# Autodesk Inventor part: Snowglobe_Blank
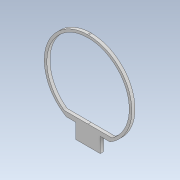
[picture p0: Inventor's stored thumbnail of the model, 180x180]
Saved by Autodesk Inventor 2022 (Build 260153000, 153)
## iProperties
Created: 2021-12
Part Number: Snowglobe_Blank
Material: Generic
Document SubType Name: Modeling
Designer: allis
Density: 1 g/cm^3
Appearance: Default
Author: allis
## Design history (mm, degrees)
sketch "Sketch1"
  geometry: L1 (50.861, -85.598)-(58.833, -85.598); L2 (58.833, -85.598)-(66.805, -85.6); L3 (66.805, -85.6)-(74.776, -85.59); L4 (74.776, -85.59)-(75.012, -85.59); L5 (75.012, -85.59)-(75.292, -85.531); L6 (75.292, -85.531)-(75.477, -85.396); L7 (75.477, -85.396)-(78.608, -83.118); L8 (78.608, -83.118)-(81.384, -80.463); L9 (81.384, -80.463)-(83.774, -77.415); L10 (83.774, -77.415)-(88.867, -70.922); L11 (88.867, -70.922)-(91.804, -63.567); L12 (91.804, -63.567)-(92.557, -55.346); L13 (92.557, -55.346)-(92.991, -50.613); L14 (92.991, -50.613)-(92.653, -45.935); L15 (92.653, -45.935)-(91.487, -41.329); L16 (91.487, -41.329)-(89.469, -33.358); L17 (89.469, -33.358)-(85.484, -26.508); L18 (85.484, -26.508)-(79.422, -20.958); L19 (79.422, -20.958)-(69.39, -11.773); L20 (69.39, -11.773)-(57.557, -8.225); L21 (57.557, -8.225)-(44.134, -10.256); L22 (44.134, -10.256)-(34.84, -11.662); L23 (34.84, -11.662)-(26.971, -15.961); L24 (26.971, -15.961)-(20.51, -22.762); L25 (20.51, -22.762)-(14.42, -29.174); L26 (14.42, -29.174)-(10.729, -36.789); L27 (10.729, -36.789)-(9.465, -45.555); L28 (9.465, -45.555)-(8.658, -51.151); L29 (8.658, -51.151)-(8.945, -56.696); L30 (8.945, -56.696)-(10.397, -62.162); L31 (10.397, -62.162)-(12.946, -71.761); L32 (12.946, -71.761)-(18.308, -79.453); L33 (18.308, -79.453)-(26.255, -85.369); L34 (26.255, -85.369)-(26.449, -85.513); L35 (26.449, -85.513)-(26.742, -85.588); L36 (26.742, -85.588)-(26.988, -85.589); L37 (26.988, -85.589)-(34.946, -85.6); L38 (34.946, -85.6)-(42.904, -85.598); L39 (42.904, -85.598)-(50.861, -85.598); L40 (38.354, -105.325)-(38.354, -100.277); L41 (38.354, -100.277)-(38.354, -95.229); L42 (38.354, -95.229)-(38.354, -90.128); L43 (38.354, -90.128)-(38.15, -90.128); L44 (38.15, -90.128)-(37.986, -90.128); L45 (37.986, -90.128)-(37.822, -90.128); L46 (37.822, -90.128)-(34.943, -90.128); L47 (34.943, -90.128)-(32.065, -90.133); L48 (32.065, -90.133)-(29.186, -90.119); L49 (29.186, -90.119)-(28.934, -90.117); L50 (28.934, -90.117)-(28.649, -90.046); L51 (28.649, -90.046)-(28.435, -89.916); L52 (28.435, -89.916)-(17.256, -83.139); L53 (17.256, -83.139)-(10.176, -73.403); L54 (10.176, -73.403)-(7.363, -60.616); L55 (7.363, -60.616)-(6.333, -55.935); L56 (6.333, -55.935)-(6.159, -51.194); L57 (6.159, -51.194)-(6.713, -46.44); L58 (6.713, -46.44)-(7.691, -38.045); L59 (7.691, -38.045)-(10.797, -30.509); L60 (10.797, -30.509)-(16.063, -23.897); L61 (16.063, -23.897)-(21.593, -16.952); L62 (21.593, -16.952)-(28.593, -12.076); L63 (28.593, -12.076)-(37.023, -9.28); L64 (37.023, -9.28)-(41.199, -7.895)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; 1 further point
  constraints: 3 other
extrude "Extrusion1" new body sketch "Sketch1" distance "d0" = 3.175; taper "d1" = 0 deg
body "Solid1"
